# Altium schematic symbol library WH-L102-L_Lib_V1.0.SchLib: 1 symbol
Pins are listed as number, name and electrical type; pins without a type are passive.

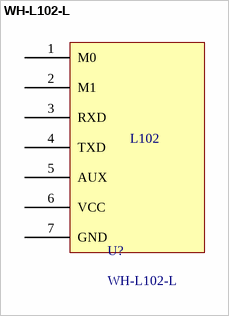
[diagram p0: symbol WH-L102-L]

## WH-L102-L
designator U?
pins: 1 M0, 2 M1, 3 RXD, 4 TXD, 5 AUX, 6 VCC, 7 GND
